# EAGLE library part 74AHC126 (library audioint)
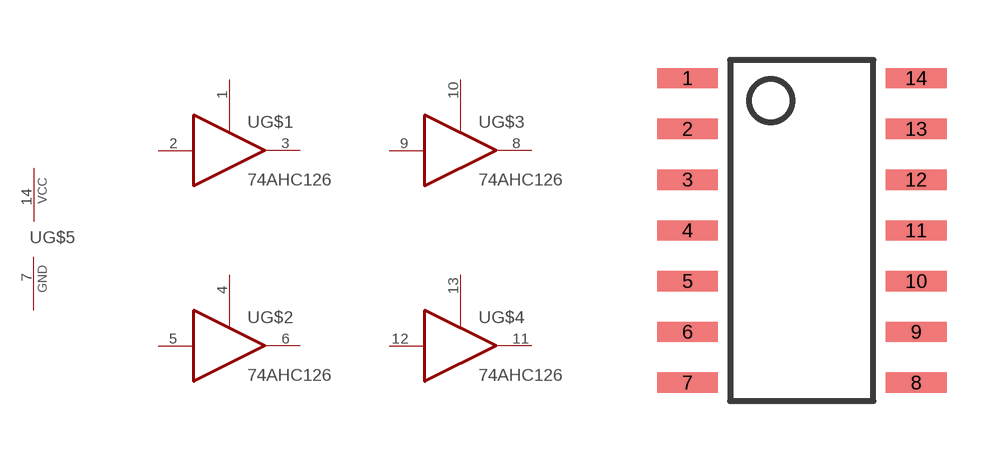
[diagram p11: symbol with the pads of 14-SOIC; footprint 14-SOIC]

Designator prefix -; gates G$1=74126 G$2=74126 G$3=74126 G$4=74126 G$5=PWR-GND

## 74AHC126  [14-SOIC]
1  G$1:OE  in
2  G$1:I  in
3  G$1:O  out
4  G$2:OE  in
5  G$2:I  in
6  G$2:O  out
7  G$5:GND  pwr
8  G$3:O  out
9  G$3:I  in
10  G$3:OE  in
11  G$4:O  out
12  G$4:I  in
13  G$4:OE  in
14  G$5:VCC  pwr

## Footprint 14-SOIC (pad centres in mm)
smd 1.524 x 0.508: 1 -2.857,3.81; 2 -2.857,2.54; 3 -2.857,1.27; 4 -2.857,0; 5 -2.857,-1.27; 6 -2.857,-2.54; 7 -2.857,-3.81; 8 2.857,-3.81; 9 2.857,-2.54; 10 2.857,-1.27; 11 2.857,0; 12 2.857,1.27; 13 2.857,2.54; 14 2.857,3.81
